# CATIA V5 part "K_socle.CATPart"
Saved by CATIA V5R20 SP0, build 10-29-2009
Part number: socle
Bounding box of the stored display mesh (mm): x -2.5 to 23.5, y -13 to 1, z -2.517 to 52.5
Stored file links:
  G:\Khaled_CFAO_2011\ST2M\ST2M_GR2\gcausse\Khaled\CAD_ThinkMotion\K_socle.CATPart
  C:\Documents and Settings\gcausse\Bureau\video thinkmotio\assemblage_gcausse\pupitre_think.CATProduct
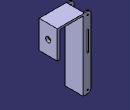
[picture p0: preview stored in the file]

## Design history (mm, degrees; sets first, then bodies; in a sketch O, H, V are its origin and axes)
Set1
  Plane1: stored without definition
  Sketch1 on Plane1, origin (0, 0, 0), H (-1, 0, 0), V (0, 0, 1)
    line L1 (-2.5, 52.5) -> (-2.5, -2.5)
    line L2 (-2.5, -2.5) -> (0, -2.5)
    arc A1 centre (0, 0) radius 2.5 from (0, -2.5) to (2.5, 0) ccw
    point P4 (0, 0)
    line L3 (2.5, 0) -> (2.5, 50)
    arc A2 centre (0, 50) radius 2.5 from (2.5, 50) to (0, 52.5) ccw
    point P7 (0, 50)
    line L4 (0, 52.5) -> (-2.5, 52.5)
    reference projected point E1 (0, 0) from Point2
    reference projected point E2 (0, 50) from Point1
    reference projected line E3 (0, 50) -> (0, 0) from Line1
    reference projected line E4 (0, 50) -> (0, 0) from Line1
    reference projected line E5 (0, 50) -> (0, 0) from Line1
    reference projected point E6 (0, 0) from Point2
    reference projected point E7 (0, 50) from Point3
    distance L1 E4 = 2.5
    distance E5 L3 = 2.5
    distance L2 E6 = 2.5
    distance E7 L4 = 2.5
    coincidence: P4 E1, P7 E2
    tangency: L3 A2, L3 A1
    parallelism: L1 E3
  Point1: stored without definition
  Sketch2 on Plane2, origin (0, -12, 0), H (-1, 0, 0), V (0, 0, 1)
    line L1 (-2.5, 52.4305) -> (-2.5, -2.5)
    line L2 (-2.5, -2.5) -> (0, -2.5)
    arc A1 centre (0, 0) radius 2.5 from (0, -2.5) to (2.4326, -0.5766) ccw
    point P4 (0, 0)
    line L3 (2.4326, -0.5766) -> (2.4326, 50)
    arc A2 centre (0, 50) radius 2.4326 from (2.4326, 50) to (-0.002, 52.4326) ccw
    point P7 (0, 50)
    line L4 (-0.002, 52.4326) -> (-2.5, 52.4305)
    reference projected point E1 (0, 50) from Point6
    reference projected point E2 (0, 0) from Point7
    reference projected line E3 (0, 50) -> (0, 0) from Line1
    reference projected line E4 (0, 50) -> (0, 0) from Line1
    distance L1 E4 = 2.5
    vertical: L1 V, L3 V
    horizontal: L2 H
    tangency: A1 L1, A1 L2, A2 L3, L4 A2
    coincidence: P7 E1, P4 E2
    parallelism: L1 E3
Set2
  Point2: linked copy from another document
  Line1: linked copy from another document
  Point3 to Point5: linked copy from another document
  Plane2: linked copy from another document
  Point6 to Point9: linked copy from another document
  Line2: linked copy from another document
Set3
  Line3: type PtPt, FirstPoint Point4, SecondPoint Point5
  Line4: type PtPt, FirstPoint Point8, SecondPoint Point9
Body1 (main body)
  Pad1: profile Sketch1, direction (0, 1, 0), length 1
  Sketch3 on end face of Pad1, origin (2.8241, 1, 43.8551), H (1, 0, 0), V (0, 0, -1)
    point P1 (-2.8241, -6.1449)
    reference projected point E1 (-2.8241, -6.1449) from Point3
    coincidence: P1 E1
  Hole1: placed by Sketch3, at (0, 1, 50) direction (0, -1, 0), diameter 1, depth 1
  Sketch4 on end face of Pad1, origin (1.7855, 1, -0.1705), H (1, 0, 0), V (0, 0, -1)
    point P1 (-1.7855, -0.1705)
    reference projected point E1 (-1.7855, -0.1705) from Point2
    coincidence: P1 E1
  Hole2: placed by Sketch4, at (0, 1, 0) direction (0, -1, 0), diameter 1, depth 1
  Sketch5 on end face of Pad1, origin (0, 1, 0), H (-1, 0, 0), V (0, 0, 1)
    line L1 (-0.5, 40) -> (-0.5, 25)
    arc A1 centre (0, 25) radius 0.5 from (-0.5, 25) to (0.5, 25) ccw
    point P3 (0, 25)
    line L2 (0.5, 25) -> (0.5, 40)
    arc A2 centre (0, 40) radius 0.5 from (0.5, 40) to (-0.5, 40) ccw
    point P6 (0, 40)
    reference projected point E1 (0, 40) from Point4
    reference projected point E2 (0, 25) from Point5
    distance L1 L2 = 1
    vertical: L1 V
    tangency: A1 L1, L2 A1, A2 L1, A2 L2
    coincidence: P6 E1, P3 E2
  Pocket1: profile Sketch5, direction (0, -1, 0), length 1
  Pad2: profile Sketch2, direction (0, -1, 0), length 1
  Sketch6 on end face of Pad2, origin (0, -13, 0), H (-1, 0, 0), V (0, 0, 1)
    line L1 (0.5, 40) -> (0.5, 25)
    arc A1 centre (0, 25) radius 0.5 from (0.5, 25) to (-0.5, 25) cw
    point P3 (0, 25)
    line L2 (-0.5, 25) -> (-0.5, 40)
    arc A2 centre (0, 40) radius 0.5 from (-0.5, 40) to (0.5, 40) cw
    point P6 (0, 40)
    reference projected point E1 (0, 40) from Point4
    reference projected point E2 (0, 25) from Point5
    distance L1 L2 = 1
    tangency: A1 L1, L2 A1, A2 L1, A2 L2
    coincidence: P6 E1, P3 E2
  Pocket2: profile Sketch6, direction (0, 1, 0), length 1
  Sketch7 on face of Pad1 from Sketch1.L1, origin (2.5, 0, 0), H (0, 1, 0), V (0, 0, 1)
    line L1 (-13, 52.5) -> (1, 52.5)
    line L2 (1, 52.5) -> (1, -2.5168)
    line L3 (1, -2.5168) -> (-13, -2.5168)
    line L4 (-13, -2.5168) -> (-13, 52.5)
    reference projected line E1 (1, 52.5) -> (1, -2.5) from edge [face of Pad1 from Sketch1.L1 | end face of Pad1]
    reference projected line E2 (0, 52.5) -> (1, 52.5) from edge [face of Pad1 from Sketch1.L1 | face of Pad1 from Sketch1.L4]
    reference projected line E3 (-13, 52.4305) -> (-13, -2.5) from edge [end face of Pad2 | face of Pad2 from Sketch2.L1]
    horizontal: L1 H, L3 H
    vertical: L2 V, L4 V
    coincidence: L2 E1, L1 E2, L4 E3
  Pad3: profile Sketch7, direction (1, 0, 0), length 1
  Sketch8 on face of Pad3, origin (2.0211, -13, 50.1452), H (1, 0, 0), V (0, 0, 1)
    point P1 (-2.0211, -0.1452)
    reference projected point E1 (-2.0211, -0.1452) from Point3
    coincidence: P1 E1
  Hole3: placed by Sketch8, at (0, -13, 50) direction (0, 1, 0), diameter 1, depth 1
  Sketch9 on face of Pad3, origin (1.9441, -13, 3.5032), H (1, 0, 0), V (0, 0, 1)
    point P1 (-1.9441, -3.5032)
    reference projected point E1 (-1.9441, -3.5032) from Point7
    coincidence: P1 E1
  Hole4: placed by Sketch9, at (0, -13, 0) direction (0, 1, 0), diameter 1, depth 1
  Sketch10 on end face of Pad3, origin (3.5, 0, 0), H (0, 1, 0), V (0, 0, 1)
    line L1 (-13, 52.5) -> (1, 52.5)
    line L2 (1, 52.5) -> (1, 51)
    line L3 (1, 51) -> (-13, 51)
    line L4 (-13, 51) -> (-13, 52.5)
    reference projected line E1 (-13, 52.5) -> (-13, -2.5168) from edge [face of Pad3 from Sketch7.L4 | end face of Pad3]
    reference projected line E2 (1, -2.5168) -> (1, 52.5) from edge [face of Pad3 from Sketch7.L2 | end face of Pad3]
    reference projected line E3 (1, 52.5) -> (-13, 52.5) from edge [face of Pad3 from Sketch7.L1 | end face of Pad3]
    reference projected line E4 (-12, 50) -> (8, 50) from Line2
    distance L3 E4 = 1
    coincidence: L4 E1, L2 E2, L1 E3
  Pad4: profile Sketch10, direction (1, 0, 0), length 20
  Sketch11 on face of Pad4 from Sketch10.L3, origin (0, 0, 51), H (1, 0, 0), V (0, -1, 0)
    line L1 (21.5, 13) -> (23.5, 13)
    line L2 (23.5, 13) -> (23.5, -1)
    line L3 (23.5, -1) -> (21.5, -1)
    line L4 (21.5, -1) -> (21.5, 13)
    reference projected line E1 (23.5, 13) -> (23.5, -1) from edge [face of Pad4 from Sketch10.L3 | end face of Pad4]
    reference projected line E2 (3.5, 13) -> (23.5, 13) from edge [face of Pad4 from Sketch10.L3 | face of Pad4]
    reference projected line E3 (3.5, -1) -> (23.5, -1) from edge [face of Pad4 | face of Pad4 from Sketch10.L3]
    distance L4 L2 = 2
    coincidence: L2 E1, L1 E2, L3 E3
  Pad5: profile Sketch11, direction (0, 0, -1), length 20
  Sketch12 on face of Pad5, origin (23.5, -3.513, 43.1377), H (0, 1, 0), V (0, 0, 1)
    point P1 (-2.487, -1.3877)
    reference projected line E1 (4.513, 7.8623) -> (4.513, 9.3623) from edge [face of Pad5 | face of Pad5]
    reference projected line E2 (-9.487, 9.3623) -> (-9.487, 7.8623) from edge [face of Pad5 | face of Pad5]
    reference projected line E3 (4.513, 9.3623) -> (-9.487, 9.3623) from edge [face of Pad4 | face of Pad5]
    reference projected line E4 (4.513, -12.1377) -> (-9.487, -12.1377) from edge [face of Pad5 | end face of Pad5]
    equidistance: E1 E2 P1, E3 E4 P1
  Hole5: placed by Sketch12, at (23.5, -6, 41.75) direction (-1, 0, 0), diameter 4, through (limit type 6)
